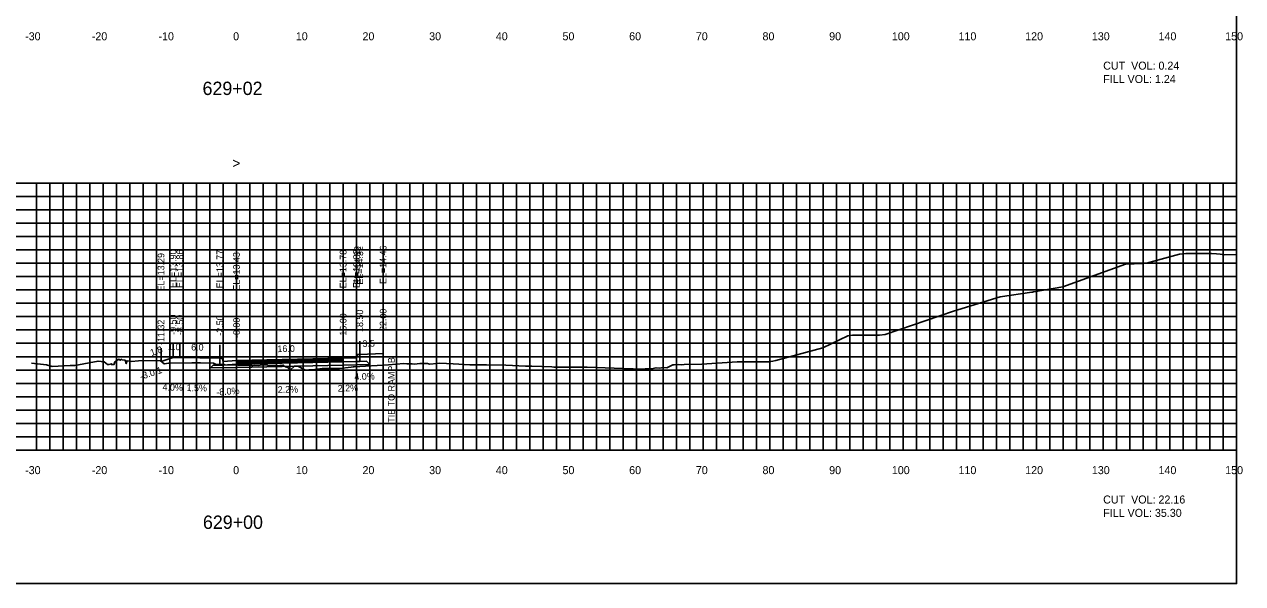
# Model space of a CAD drawing. Extents: x 1797645 to 1803805, y 248417 to 250269.
# Drawn here: x 1802939.2 to 1803121.9, y 250079.4 to 250163.2 of the extents above; entities that cross this region are included whole.
import ezdxf

# ---------------------------------------------------------------- set-up
doc = ezdxf.new("R2010")
doc.units = 0
for name, color, linetype in [('1', 7, 'Continuous'), ('10', 7, 'Continuous'), ('3', 7, 'Continuous'), ('4', 7, 'Continuous'), ('60', 7, 'Continuous'), ('ANNO-TXT', 7, 'Continuous'), ('BASE', 7, 'Continuous'), ('CL-CNST', 7, 'Continuous'), ('Level 62', 7, 'Continuous'), ('LOWER BINDER', 7, 'Continuous'), ('M-ROADS', 7, 'Continuous'), ('UPPER BINDER', 7, 'Continuous'), ('WEARING', 7, 'Continuous')]:
    doc.layers.add(name, color=color, linetype=linetype)

msp = doc.modelspace()

# ---------------------------------------------------------------- linework, layer by layer
for p, q in [((1802961.5, 250113.33), (1802961.5, 250115.33)), ((1802962.5, 250113.29), (1802962.5, 250115.29)), ((1802968.5, 250113.2), (1802968.5, 250115.2)), ((1802968.5, 250113.2), (1802968.5, 250115.2)), ((1802987, 250113.21), (1802987, 250115.21)), ((1802989.5, 250113.76), (1802989.5, 250115.76)), ((1802993, 250113.9), (1802993, 250115.9)), ((1802959.68, 250112.72), (1802959.68, 250114.72)), ((1802971, 250112.86), (1802971, 250114.86))]:
    msp.add_line(p, q)
for points in [[(1802821, 250079.43), (1803121, 250079.43), (1803121, 250269.43), (1802821, 250269.43)], [(1802987, 250113.21), (1802989, 250113.26), (1802989.17, 250113.76), (1802989.5, 250113.76), (1802989.5, 250112.73), (1802989, 250112.73), (1802987, 250112.68)], [(1802971, 250112.86), (1802969, 250112.7), (1802968.83, 250113.2), (1802968.5, 250113.2), (1802968.5, 250112.17), (1802969, 250112.17), (1802971, 250112.33)]]:
    msp.add_lwpolyline(points, close=True)
at = {"layer": '3'}
msp.add_line((1802993, 250113.9), (1802993, 250107.11), dxfattribs=at)
at = {"layer": '60'}
for p, q in [((1803121, 250099.43), (1803121, 250139.43)), ((1803121.06, 250139.43), (1803121, 250139.43)), ((1803121.06, 250129.43), (1803121, 250129.43)), ((1803121.06, 250119.43), (1803121, 250119.43)), ((1803121.06, 250109.43), (1803121, 250109.43)), ((1802821, 250099.43), (1803121, 250099.43)), ((1802941, 250099.37), (1802941, 250099.43)), ((1802951, 250099.37), (1802951, 250099.43)), ((1802961, 250099.37), (1802961, 250099.43)), ((1802971, 250099.37), (1802971, 250099.43)), ((1802981, 250099.37), (1802981, 250099.43)), ((1802991, 250099.37), (1802991, 250099.43)), ((1803001, 250099.37), (1803001, 250099.43)), ((1803011, 250099.37), (1803011, 250099.43)), ((1803021, 250099.37), (1803021, 250099.43)), ((1803031, 250099.37), (1803031, 250099.43)), ((1803041, 250099.37), (1803041, 250099.43)), ((1803051, 250099.37), (1803051, 250099.43)), ((1803061, 250099.37), (1803061, 250099.43)), ((1803071, 250099.37), (1803071, 250099.43)), ((1803081, 250099.37), (1803081, 250099.43)), ((1803091, 250099.37), (1803091, 250099.43)), ((1803101, 250099.37), (1803101, 250099.43)), ((1803111, 250099.37), (1803111, 250099.43)), ((1803121, 250099.37), (1803121, 250099.43)), ((1803121.06, 250099.43), (1803121, 250099.43))]:
    msp.add_line(p, q, dxfattribs=at)
at = {"layer": 'BASE'}
msp.add_lwpolyline([(1802971, 250112.33), (1802987, 250112.68), (1802989, 250112.73), (1802989.5, 250112.73), (1802990.5, 250112.75), (1802990.98, 250112.27), (1802987, 250112.18), (1802971, 250111.83), (1802967.09, 250111.74), (1802967.5, 250112.15), (1802968.5, 250112.17), (1802969, 250112.17)], close=True, dxfattribs=at)
at = {"layer": 'CL-CNST'}
msp.add_lwpolyline([(1802959.68, 250112.72), (1802961.5, 250113.33), (1802962.5, 250113.29), (1802968.5, 250113.2), (1802968.5, 250113.2), (1802968.83, 250113.2), (1802969, 250112.7), (1802971, 250112.86), (1802987, 250113.21), (1802989, 250113.26), (1802989.17, 250113.76), (1802989.5, 250113.76), (1802993, 250113.9)], dxfattribs=at)
at = {"layer": 'Level 62'}
for p, q in [((1802821, 250139.43), (1803121, 250139.43)), ((1802941, 250099.43), (1802941, 250139.43)), ((1802943, 250099.43), (1802943, 250139.43)), ((1802945, 250099.43), (1802945, 250139.43)), ((1802947, 250099.43), (1802947, 250139.43)), ((1802949, 250099.43), (1802949, 250139.43)), ((1802951, 250099.43), (1802951, 250139.43)), ((1802953, 250099.43), (1802953, 250139.43)), ((1802955, 250099.43), (1802955, 250139.43)), ((1802957, 250099.43), (1802957, 250139.43)), ((1802959, 250099.43), (1802959, 250139.43)), ((1802961, 250099.43), (1802961, 250139.43)), ((1802963, 250099.43), (1802963, 250139.43)), ((1802965, 250099.43), (1802965, 250139.43)), ((1802967, 250099.43), (1802967, 250139.43)), ((1802969, 250099.43), (1802969, 250139.43)), ((1802971, 250099.43), (1802971, 250139.43)), ((1802973, 250099.43), (1802973, 250139.43)), ((1802975, 250099.43), (1802975, 250139.43)), ((1802977, 250099.43), (1802977, 250139.43)), ((1802979, 250099.43), (1802979, 250139.43)), ((1802981, 250099.43), (1802981, 250139.43)), ((1802983, 250099.43), (1802983, 250139.43)), ((1802985, 250099.43), (1802985, 250139.43)), ((1802987, 250099.43), (1802987, 250139.43)), ((1802989, 250099.43), (1802989, 250139.43)), ((1802991, 250099.43), (1802991, 250139.43)), ((1802993, 250099.43), (1802993, 250139.43)), ((1802995, 250099.43), (1802995, 250139.43)), ((1802997, 250099.43), (1802997, 250139.43)), ((1802999, 250099.43), (1802999, 250139.43)), ((1803001, 250099.43), (1803001, 250139.43)), ((1803003, 250099.43), (1803003, 250139.43)), ((1803005, 250099.43), (1803005, 250139.43)), ((1803007, 250099.43), (1803007, 250139.43)), ((1803009, 250099.43), (1803009, 250139.43)), ((1803011, 250099.43), (1803011, 250139.43)), ((1803013, 250099.43), (1803013, 250139.43)), ((1803015, 250099.43), (1803015, 250139.43)), ((1803017, 250099.43), (1803017, 250139.43)), ((1803019, 250099.43), (1803019, 250139.43)), ((1803021, 250099.43), (1803021, 250139.43)), ((1803023, 250099.43), (1803023, 250139.43)), ((1803025, 250099.43), (1803025, 250139.43)), ((1803027, 250099.43), (1803027, 250139.43)), ((1803029, 250099.43), (1803029, 250139.43)), ((1803031, 250099.43), (1803031, 250139.43)), ((1803033, 250099.43), (1803033, 250139.43)), ((1803035, 250099.43), (1803035, 250139.43)), ((1803037, 250099.43), (1803037, 250139.43)), ((1803039, 250099.43), (1803039, 250139.43)), ((1803041, 250099.43), (1803041, 250139.43)), ((1803043, 250099.43), (1803043, 250139.43)), ((1803045, 250099.43), (1803045, 250139.43)), ((1803047, 250099.43), (1803047, 250139.43)), ((1803049, 250099.43), (1803049, 250139.43)), ((1803051, 250099.43), (1803051, 250139.43)), ((1803053, 250099.43), (1803053, 250139.43)), ((1803055, 250099.43), (1803055, 250139.43)), ((1803057, 250099.43), (1803057, 250139.43)), ((1803059, 250099.43), (1803059, 250139.43)), ((1803061, 250099.43), (1803061, 250139.43)), ((1803063, 250099.43), (1803063, 250139.43)), ((1803065, 250099.43), (1803065, 250139.43)), ((1803067, 250099.43), (1803067, 250139.43)), ((1803069, 250099.43), (1803069, 250139.43)), ((1803071, 250099.43), (1803071, 250139.43)), ((1803073, 250099.43), (1803073, 250139.43)), ((1803075, 250099.43), (1803075, 250139.43)), ((1803077, 250099.43), (1803077, 250139.43)), ((1803079, 250099.43), (1803079, 250139.43)), ((1803081, 250099.43), (1803081, 250139.43)), ((1803083, 250099.43), (1803083, 250139.43)), ((1803085, 250099.43), (1803085, 250139.43)), ((1803087, 250099.43), (1803087, 250139.43)), ((1803089, 250099.43), (1803089, 250139.43)), ((1803091, 250099.43), (1803091, 250139.43)), ((1803093, 250099.43), (1803093, 250139.43)), ((1803095, 250099.43), (1803095, 250139.43)), ((1803097, 250099.43), (1803097, 250139.43)), ((1803099, 250099.43), (1803099, 250139.43)), ((1803101, 250099.43), (1803101, 250139.43)), ((1803103, 250099.43), (1803103, 250139.43)), ((1803105, 250099.43), (1803105, 250139.43)), ((1803107, 250099.43), (1803107, 250139.43)), ((1803109, 250099.43), (1803109, 250139.43)), ((1803111, 250099.43), (1803111, 250139.43)), ((1803113, 250099.43), (1803113, 250139.43)), ((1803115, 250099.43), (1803115, 250139.43)), ((1803117, 250099.43), (1803117, 250139.43)), ((1803119, 250099.43), (1803119, 250139.43)), ((1803121, 250099.43), (1803121, 250139.43)), ((1802821, 250137.43), (1803121, 250137.43)), ((1802821, 250135.43), (1803121, 250135.43)), ((1802821, 250133.43), (1803121, 250133.43)), ((1802821, 250131.43), (1803121, 250131.43)), ((1802821, 250129.43), (1803121, 250129.43)), ((1802821, 250127.43), (1803121, 250127.43)), ((1802821, 250125.43), (1803121, 250125.43)), ((1802821, 250123.43), (1803121, 250123.43)), ((1802821, 250121.43), (1803121, 250121.43)), ((1802821, 250119.43), (1803121, 250119.43)), ((1802821, 250117.43), (1803121, 250117.43)), ((1802821, 250115.43), (1803121, 250115.43)), ((1802821, 250113.43), (1803121, 250113.43)), ((1802821, 250111.43), (1803121, 250111.43)), ((1802821, 250109.43), (1803121, 250109.43)), ((1802821, 250107.43), (1803121, 250107.43)), ((1802821, 250105.43), (1803121, 250105.43)), ((1802821, 250103.43), (1803121, 250103.43)), ((1802821, 250101.43), (1803121, 250101.43)), ((1802821, 250099.43), (1803121, 250099.43))]:
    msp.add_line(p, q, dxfattribs=at)
at = {"layer": 'LOWER BINDER'}
msp.add_lwpolyline([(1802987, 250112.68), (1802987, 250112.68), (1802987, 250112.87), (1802971, 250112.52), (1802971, 250112.33)], close=True, dxfattribs=at)
at = {"layer": 'M-ROADS'}
msp.add_lwpolyline([(1802940.25, 250112.46), (1802942.5, 250112.2), (1802943.34, 250111.97), (1802946.07, 250112.13), (1802946.75, 250112.12), (1802950.24, 250112.76), (1802951.18, 250112.68), (1802951.64, 250112.24), (1802951.69, 250112.24), (1802951.78, 250112.24), (1802951.86, 250112.25), (1802952.25, 250112.37), (1802952.28, 250112.21), (1802952.4, 250112.25), (1802952.63, 250112.28), (1802952.65, 250112.27), (1802952.65, 250112.39), (1802952.66, 250112.29), (1802952.74, 250112.65), (1802953.38, 250113.05), (1802953.57, 250112.9), (1802953.75, 250113.05), (1802953.88, 250112.97), (1802954.29, 250112.89), (1802954.48, 250112.39), (1802954.59, 250112.83), (1802955.26, 250112.72), (1802956.32, 250112.79), (1802959.54, 250112.84), (1802960.16, 250112.34), (1802960.84, 250112.46), (1802961.11, 250112.45), (1802964.31, 250112.49), (1802964.95, 250112.49), (1802965.58, 250112.49), (1802967.57, 250112.46), (1802967.84, 250112.33), (1802968.92, 250112.27), (1802969.1, 250112.24), (1802969.17, 250112.24), (1802969.25, 250112.23), (1802973.17, 250112.13), (1802973.32, 250112.13), (1802973.45, 250112.13), (1802973.76, 250112.15), (1802974.28, 250112.13), (1802974.81, 250112.21), (1802975.62, 250112.21), (1802975.73, 250112.12), (1802976.25, 250112.13), (1802976.92, 250112.13), (1802977.11, 250112.08), (1802977.52, 250112.09), (1802977.83, 250112.09), (1802977.92, 250112.07), (1802978.01, 250112.19), (1802978.32, 250111.89), (1802978.71, 250111.79), (1802979.06, 250111.4), (1802979.73, 250112.04), (1802980.19, 250112.03), (1802981.25, 250111.47), (1802981.81, 250111.4), (1802981.92, 250111.46), (1802982.35, 250111.45), (1802983.83, 250111.65), (1802984.02, 250111.64), (1802984.13, 250111.64), (1802984.61, 250111.64), (1802986.46, 250111.65), (1802988.19, 250111.86), (1802988.51, 250111.9), (1802988.67, 250111.9), (1802993.78, 250112.21), (1802994.96, 250112.33), (1802996.1, 250112.41), (1802996.57, 250112.35), (1802997.08, 250112.35), (1802997.17, 250112.35), (1802997.37, 250112.34), (1802997.7, 250112.33), (1802998.5, 250112.39), (1802999.64, 250112.41), (1802999.96, 250112.33), (1803001.11, 250112.41), (1803001.52, 250112.44), (1803003.48, 250112.36), (1803006.01, 250112.21), (1803007.44, 250112.21), (1803008.52, 250112.19), (1803009.12, 250112.18), (1803011.01, 250112.21), (1803011.41, 250112.15), (1803014.34, 250112.03), (1803014.82, 250112.03), (1803015.29, 250112.03), (1803018.3, 250111.9), (1803018.59, 250111.87), (1803019.62, 250111.87), (1803021.13, 250111.85), (1803021.27, 250111.85), (1803023.59, 250111.87), (1803029.02, 250111.65), (1803030.49, 250111.59), (1803030.74, 250111.57), (1803032.28, 250111.62), (1803033.02, 250111.62), (1803033.25, 250111.6), (1803033.94, 250111.76), (1803034.5, 250111.71), (1803035.01, 250111.8), (1803035.55, 250111.77), (1803036.45, 250112.21), (1803036.63, 250112.22), (1803037.29, 250112.26), (1803037.79, 250112.22), (1803038.17, 250112.26), (1803040.8, 250112.32), (1803046.1, 250112.66), (1803046.24, 250112.65), (1803046.46, 250112.66), (1803048.68, 250112.66), (1803050.89, 250112.66), (1803051.1, 250112.7), (1803051.45, 250112.77), (1803051.88, 250112.85), (1803058.93, 250114.76), (1803062.68, 250116.53), (1803063.38, 250116.63), (1803065.41, 250116.63), (1803067.44, 250116.63), (1803068.29, 250116.75), (1803078.55, 250120.23), (1803085.56, 250122.42), (1803090.31, 250123.09), (1803090.39, 250123.1), (1803090.55, 250123.15), (1803090.6, 250123.16), (1803094.97, 250123.9), (1803104.35, 250127.27), (1803106.99, 250127.41), (1803107.48, 250127.44), (1803112.44, 250128.8), (1803113.42, 250128.9), (1803115.34, 250128.9), (1803117.25, 250128.9), (1803118.02, 250128.85), (1803118.53, 250128.79), (1803119.17, 250128.7), (1803121, 250128.76)], dxfattribs=at)
at = {"layer": 'UPPER BINDER'}
msp.add_lwpolyline([(1802987, 250112.87), (1802987, 250113.06), (1802971, 250112.71), (1802971, 250112.52)], close=True, dxfattribs=at)
at = {"layer": 'WEARING'}
msp.add_lwpolyline([(1802987, 250113.06), (1802987, 250113.21), (1802971, 250112.86), (1802971, 250112.71)], close=True, dxfattribs=at)

# ---------------------------------------------------------------- texts
msp.add_text('-3.0:1', height=1, rotation=18.4349).set_placement((1802956.68, 250109.94))
at = {"layer": '1'}
for s, p in [('629+02', (1802965.91, 250152.63)), ('629+00', (1802965.97, 250087.63))]:
    msp.add_text(s, height=2, dxfattribs=at).set_placement(p)
at = {"layer": '10'}
for s, p in [('-30', (1802939.3, 250160.83)), ('-20', (1802949.3, 250160.83)), ('-10', (1802959.3, 250160.83)), ('0', (1802970.5, 250160.83)), ('10', (1802979.9, 250160.83)), ('20', (1802989.9, 250160.83)), ('30', (1802999.9, 250160.83)), ('40', (1803009.9, 250160.83)), ('50', (1803019.9, 250160.83)), ('60', (1803029.9, 250160.83)), ('70', (1803039.9, 250160.83)), ('80', (1803049.9, 250160.83)), ('90', (1803059.9, 250160.83)), ('100', (1803069.3, 250160.83)), ('110', (1803079.3, 250160.83)), ('120', (1803089.3, 250160.83)), ('130', (1803099.3, 250160.83)), ('140', (1803109.3, 250160.83)), ('150', (1803119.3, 250160.83)), ('-30', (1802939.3, 250095.83)), ('-20', (1802949.3, 250095.83)), ('-10', (1802959.3, 250095.83)), ('0', (1802970.5, 250095.83)), ('10', (1802979.9, 250095.83)), ('20', (1802989.9, 250095.83)), ('30', (1802999.9, 250095.83)), ('40', (1803009.9, 250095.83)), ('50', (1803019.9, 250095.83)), ('60', (1803029.9, 250095.83)), ('70', (1803039.9, 250095.83)), ('80', (1803049.9, 250095.83)), ('90', (1803059.9, 250095.83)), ('100', (1803069.3, 250095.83)), ('110', (1803079.3, 250095.83)), ('120', (1803089.3, 250095.83)), ('130', (1803099.3, 250095.83)), ('140', (1803109.3, 250095.83)), ('150', (1803119.3, 250095.83))]:
    msp.add_text(s, height=1.2, dxfattribs=at).set_placement(p)
at = {"layer": '3'}
for s, p in [('EL=14.32', (1802989.67, 250124.23)), ('EL=14.32', (1802990, 250124.23)), ('EL=14.46', (1802993.5, 250124.32)), ('EL=13.29', (1802960.18, 250123.2)), ('EL=13.90', (1802962, 250123.72)), ('EL=13.86', (1802963, 250123.71)), ('EL=13.77', (1802969, 250123.67)), ('EL=13.77', (1802969, 250123.67)), ('EL=13.43', (1802971.5, 250123.33)), ('EL=13.78', (1802987.5, 250123.68)), ('EL=13.82', (1802989.5, 250123.73)), ('22.00', (1802993.5, 250117.27)), ('-11.32', (1802960.18, 250115.18)), ('-9.50', (1802962, 250116.7)), ('-8.50', (1802963, 250116.66)), ('-2.50', (1802969, 250116.57)), ('-2.50', (1802969, 250116.57)), ('-0.00', (1802971.5, 250116.23)), ('16.00', (1802987.5, 250116.58)), ('18.50', (1802990, 250117.13)), ('TIE TO RAMP B', (1802994.74, 250103.54))]:
    msp.add_text(s, height=1, rotation=90, dxfattribs=at).set_placement(p)
at = {"layer": '4'}
for s, rotation, p in [('1.0', 357.7094, (1802960.72, 250114.46)), ('6.0', 359.1406, (1802964.2, 250114.36)), ('16.0', 1.2603, (1802977.16, 250114.1)), ('3.5', 2.2906, (1802989.92, 250114.87)), ('1.8', 18.4349, (1802958.25, 250113.51)), ('4.0%', 2.2906, (1802988.7, 250109.9)), ('4.0%', 357.7094, (1802959.89, 250108.39)), ('1.5%', 359.1406, (1802963.51, 250108.27)), ('-8.0%', 4.5739, (1802968, 250107.6)), ('2.2%', 1.2603, (1802977.2, 250107.99)), ('2.2%', 1.2603, (1802986.2, 250108.19))]:
    msp.add_text(s, height=1, rotation=rotation, dxfattribs=at).set_placement(p)
at = {"layer": '60'}
msp.add_text('>', height=1.5, dxfattribs=at).set_placement((1802970.39, 250141.68))
at = {"layer": 'ANNO-TXT'}
for s, p in [('CUT  VOL: 0.24', (1803101, 250156.43)), ('FILL VOL: 1.24', (1803101, 250154.43)), ('CUT  VOL: 22.16', (1803101, 250091.43)), ('FILL VOL: 35.30', (1803101, 250089.43))]:
    msp.add_text(s, height=1.2, dxfattribs=at).set_placement(p)

doc.saveas('drawing.dxf')
